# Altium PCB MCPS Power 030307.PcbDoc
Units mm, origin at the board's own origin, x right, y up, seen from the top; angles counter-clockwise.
Board outline 144.17 x 67.63 mm, 2 copper layers (Top Layer, Bottom Layer); 51 components, 22 nets, 115 pads, 4 vias.
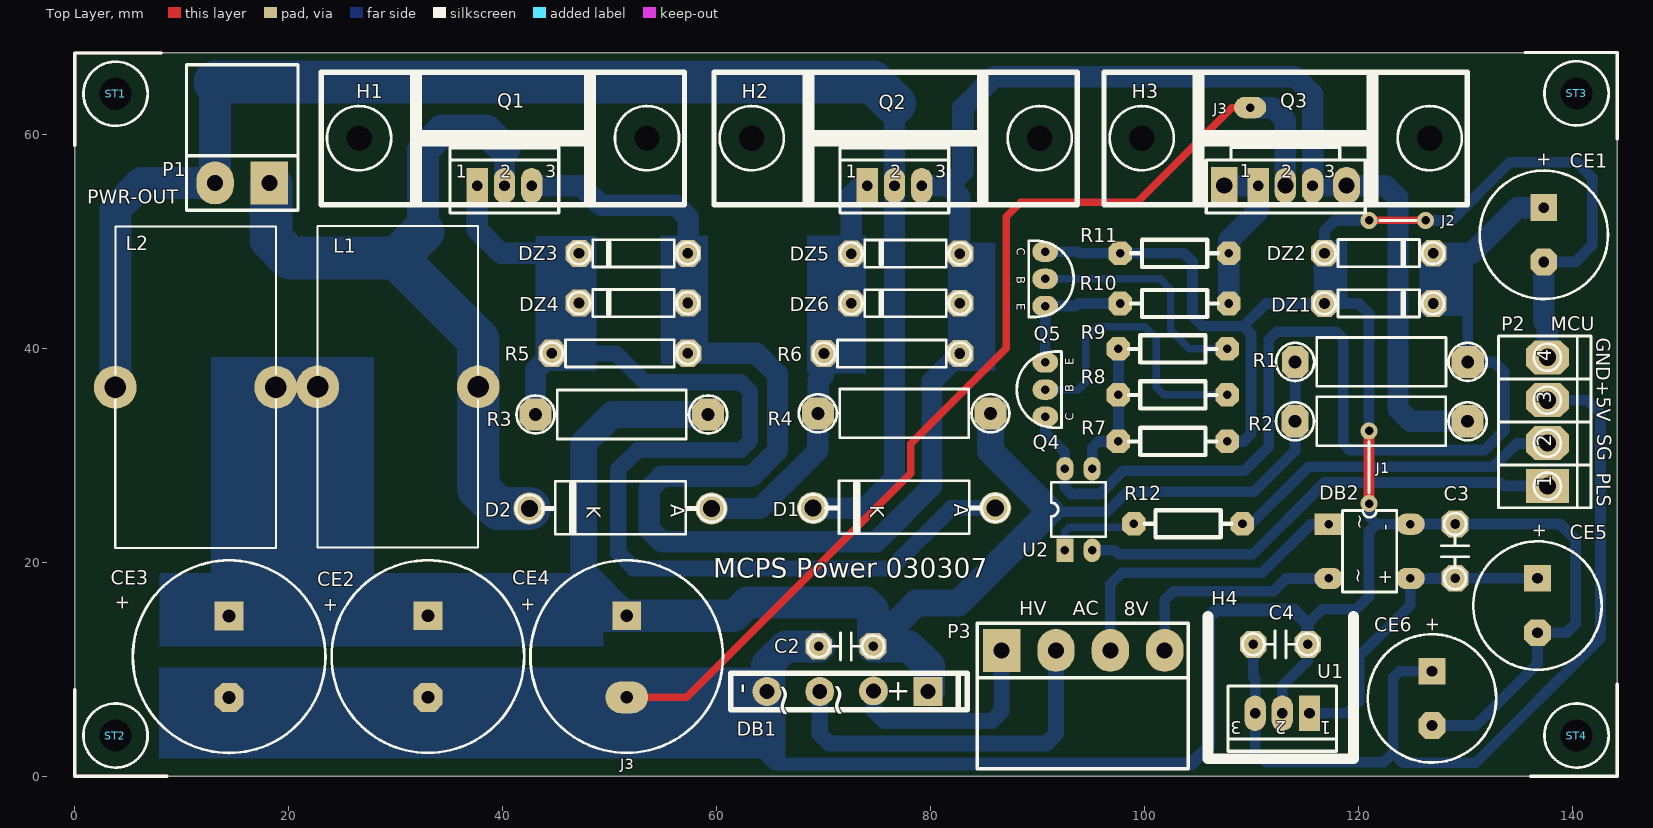
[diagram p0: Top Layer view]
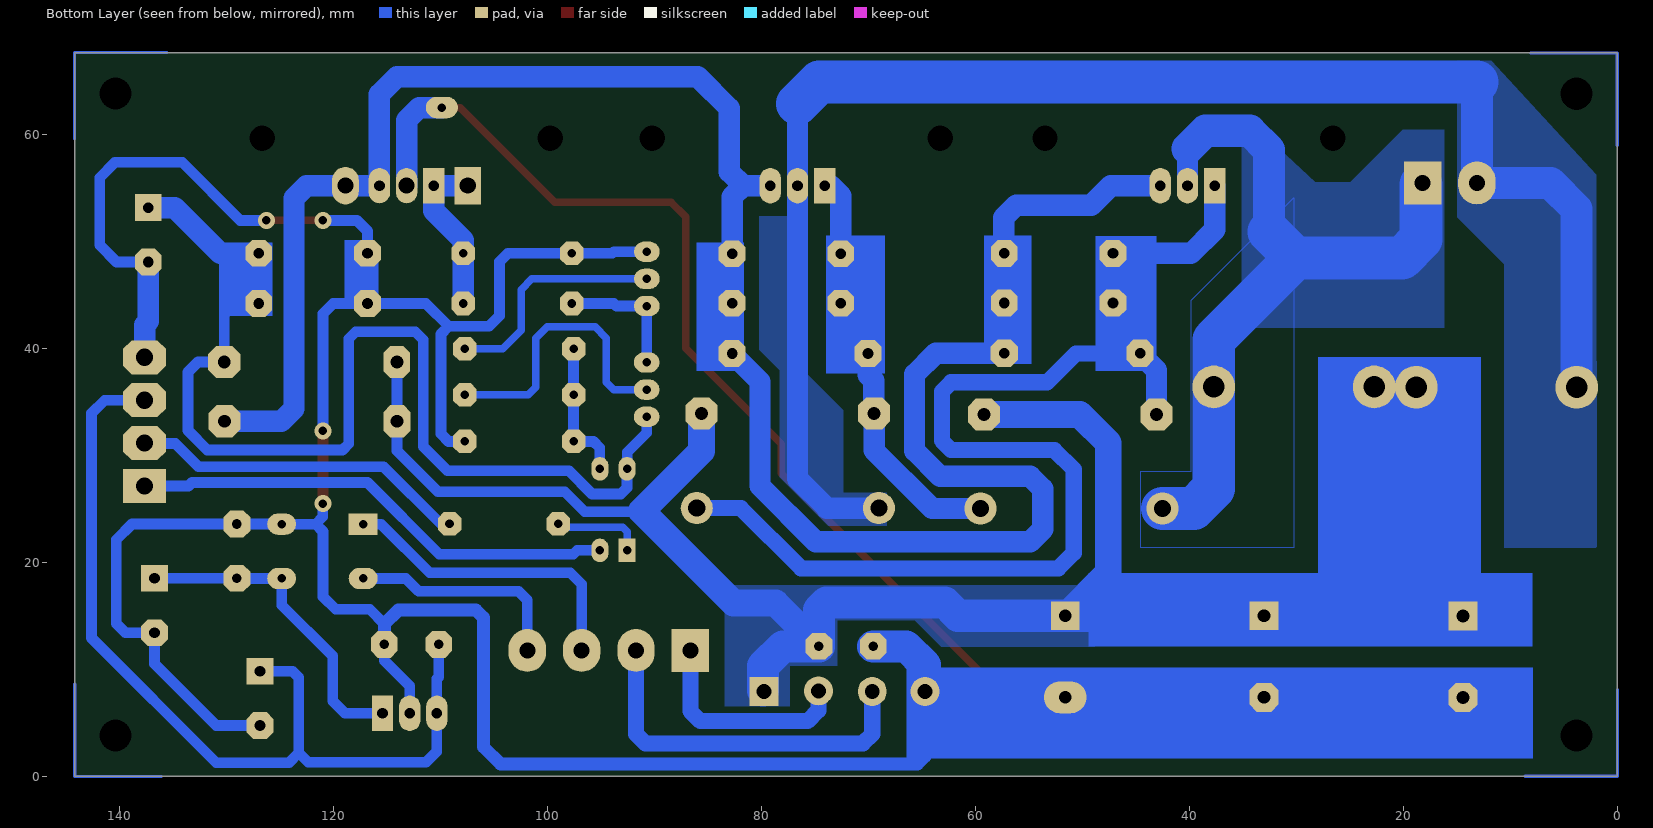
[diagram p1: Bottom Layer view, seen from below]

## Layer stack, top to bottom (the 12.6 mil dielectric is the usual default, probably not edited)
Top Solder: solder mask 0.0102, Solder Resist, Dk 3.5
Top Layer: signal copper 0.0356
Dielectric1: dielectric 0.32, FR-4, Dk 4.8
Bottom Layer: signal copper 0.0356
Bottom Solder: solder mask 0.0102, Solder Resist, Dk 3.5

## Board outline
0,-0.01 0,67.62 144.17,67.62 144.17,-0.01

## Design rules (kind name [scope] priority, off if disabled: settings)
Clearance [All] p1: gap=0.3 ignorepadtopadclearanceinfootprint=FALSE
ComponentClearance [All] p1 off: gap=0.254 collisioncheckmode=3 verticalgap=0.254 showdistances=FALSE
PolygonConnect [All] p1: connectstyle=Direct reliefconductorwidth=1 reliefentries=4 polygonreliefangle="90 Angle" airgapwidth=0.3
RoutingVias [All] p1: holewidth=0.711 width=1.27 viastyle="Through Hole" minholewidth=0.711 minwidth=1.27 maxholewidth=0.711 maxwidth=1.27
SilkToSolderMaskClearance SilkscreenOverComponentPads [IsPad] p1: minsilkscreentomaskgap=0.254 clearancetoexposedcopper=TRUE
SolderMaskExpansion [All] p1: expansion=0.102 istentingtop=FALSE
UnRoutedNet [All] p1: checkbadconnections=TRUE
Width [All] p1: maxlimit=5 minlimit=0.3 preferedwidth=0.7 minimp=50.000000 maximp=50.000000 favimp=50.000000
27 further rules are at their usual default settings.

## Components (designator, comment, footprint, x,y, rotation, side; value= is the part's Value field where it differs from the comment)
C2 "100N" c2P 74.62,12.15 r180 top locked
C3 "100N" c2P 129.01,18.5 r90 top locked
C4 "100N" c2P 110.15,12.33 r0 top locked
CE1 "470M/25" cap2p12 137.33,53.15 r0 top locked
CE2 "4700M/50" CAP3P5#1 33.01,14.85 r0 top locked
CE3 "4700M/50" CAP3P5#1 14.43,14.838 r0 top locked
CE4 "4700M/50" CAP3P5#2 51.59,14.85 r0 top locked
CE5 "1000M/25" cap2p12 136.735,18.5 r0 top locked
CE6 "220M/25" cap2p12 126.88,9.82 r0 top locked
D1 "1N5822" D54 86.03,25.07 r270 top locked
D2 "1N5822" D54 59.52,25.03 r270 top locked
DB1 "4Amp" "BRG GBU" 64.703,7.93 r270 top locked
DB2 "4Amp" "BRG F" 121.02,21.03 r90 top locked
DZ1 "18V" D4P 116.801,44.191 r180 top locked
DZ2 "18V" D4P 116.801,48.89 r180 top locked
DZ3 "18V" D4P 57.297,48.872 r0 top locked
DZ4 "18V" D4P 57.297,44.232 r0 top locked
DZ5 "18V" D4P 82.73,48.85 r0 top locked
DZ6 "18V" D4P 82.73,44.21 r0 top locked
H1 "HeatSink-Q1" heatsink2 56.957,65.782 r90 top locked
H2 "HeatSink-Q2" heatsink2 93.66,65.782 r90 top locked
H3 "HeatSink-Q3" heatsink2 130.109,65.782 r90 top locked
H4 "HeatSink-U1" heatsink5 115.282,5.977 r180 top locked
L1 "100uH/1A" Inductor-Brown 37.681,29.684 r90 top locked
L2 "100uH/1A" Inductor-Brown 3.819,43.066 r270 top locked
P1 "120Vpp/10KHz" 2EDG 19.24,75.409 r0 top locked
P2 "MCU" DSIP4 137.64,27.124 r180 top locked
P3 "40,8 Vac" 4EDG 86.63,11.76 r180 top locked
Q1 "" TO220T#1 37.626,55.198 r0 top locked
Q2 "IRFP4568" TO220T#1 74.075,55.198 r0 top locked
Q3 "IRFP4568" TO220T#2 110.61,55.2 r0 top locked
Q4 "BC337" CBE-BC546 90.71,38.68 r180 top locked
Q5 "BC327" CBE-BC546 90.7,43.95 r0 top locked
R1 "1K/1W" w1#1 122.125,38.73 r0 top locked
R2 "2K2/1W" w1#1 122.114,33.18 r0 top locked
R3 "1K/1W" w1#2 51.134,33.816 r180 top locked
R4 "1K/1W" w1#2 77.523,33.921 r180 top locked
R5 "10K" R5P 44.597,39.533 r0 top locked
R6 "4K7" R5P 82.73,39.51 r180 top locked
R7 "2K2" R4P 97.55,31.3 r90 top locked
R8 "220R" R4P 97.55,35.64 r90 top locked
R9 "220R" R4P 97.55,39.94 r90 top locked
R10 "47R" R4P 97.71,44.19 r90 top locked
R11 "10K" R4P 97.71,48.88 r90 top locked
R12 "1K" R4P 109.14,23.6 r270 top locked
ST1 "STUD" CORNER 0.01,67.6 r0 top locked
ST2 "STUD" CORNER 0,0 r90 top locked
ST3 "STUD" CORNER 144.17,67.64 r270 top locked
ST4 "STUD" CORNER 144.17,0 r180 top locked
U1 "LM7805" TO220T#1 115.4,5.89 r180 top locked
U2 "PC817" DIP4 92.55,21.12 r90 top locked

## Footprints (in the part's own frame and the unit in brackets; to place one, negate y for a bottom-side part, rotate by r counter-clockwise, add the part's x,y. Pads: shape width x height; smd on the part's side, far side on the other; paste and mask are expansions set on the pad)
2EDG [mm]
  rect 3.5x4 hole 1.5: 1(-1.045,-19.957)
  oval 3.5x4 hole 1.5: 2(-6.125,-19.957)
  silkscreen extent -8.79,-22.5 1.62,-8.91
4EDG [mm]
  rect 3.5x4 hole 1.5: 1(0,0)
  oval 3.5x4 hole 1.5: 2(-5.08,0) 3(-10.16,0) 4(-15.24,0)
  silkscreen extent -17.44,-2.54 2.29,11.05
"BRG F" [mm]
  rect 2x2.7 hole 0.8: 1(2.54,3.81)
  oval 2x2.7 hole 0.8: 2(2.54,-3.81) 3(-2.54,3.81) 4(-2.54,-3.81)
  silkscreen extent -3.81,-2.54 3.81,2.54
"BRG GBU" [mm]
  round 2.7 hole 1.4: 1(0,4.928) 2(0,0) 3(-0.051,9.957)
  rect 2.7x2.7 hole 1.4: 4(0,15.037)
  silkscreen extent -1.7,-3.41 1.7,18.69
c2P [mm]
  oct 2.5x2.5 hole 0.9: 1(0,0) 2(5.08,0)
  silkscreen extent -1.02,-1.27 6.09,1.27
cap2p12 [mm]
  rect 2.5x2.5 hole 1: 1(-0.025,0)
  oct 2.5x2.5 hole 1: 2(-0.025,-5.08)
  silkscreen extent -6.02,-8.54 5.97,3.46
CAP3P5#1 [mm]
  rect 2.7x2.7 hole 1.2: 1(0,0.152)
  oct 2.7x2.7 hole 1.2: 2(0,-7.468)
  silkscreen extent -9,-12.66 9,5.34
CAP3P5#2 [mm]
  rect 2.7x2.7 hole 1.2: 1(0,0.152)
  oval 4x3 hole 1.2: 2(0,-7.468)
  silkscreen extent -9,-12.66 9,5.34
CBE-BC546 [mm]
  oval 2.4x1.9 hole 0.8: 1(0,2.54) 2(0,0) 3(0,5.08)
  silkscreen extent -1.52,-1.02 2.67,6.1
CORNER [mm]
  round 2 hole 3: 1(3.81,-3.81)
  Multi-Layer lines w0.3: 0,-8.623 0,0.013 8.09,0.013
  silkscreen extent 0,-8.62 8.09,0.01
D4P [mm]
  oct 2.5x2.5 hole 1: 1(0,0) 2(-10.16,0)
  silkscreen extent -11.18,-1.27 1.01,1.27
D54 [mm]
  round 3 hole 1.6: 1(0,0) 2(0,-17.018)
  silkscreen extent -2.54,-18.28 2.41,1.27
DIP4 [mm]
  rect 2.2x1.6 hole 0.8: 1(0,0)
  oval 2.2x1.6 hole 0.8: 2(0,-2.54) 3(7.62,-2.54) 4(7.62,0)
  silkscreen extent 1.27,-3.81 6.35,1.27
DSIP4 [mm]
  rect 4x3.175 hole 1.6: 1(0,0)
  oct 4x3.175 hole 1.6: 2(0,-4.013) 3(0,-8.026) 4(0,-12.04)
  silkscreen extent -4.06,-14.02 4.57,2.03
heatsink2 [mm]
  round 0 hole 2.37: 5(-6.139,30.38) 5(-6.139,3.47)
  silkscreen extent -12.37,-0.04 0.03,33.91
heatsink5 [mm]
  silkscreen extent -4.23,-8.97 9.37,4.33, body extent -3.88,-8.83 9.33,3.87, height 20.32
Inductor-Brown [mm]
  round 4 hole 2: 1(6.706,14.961) 2(6.706,-0.025)
  silkscreen extent -8.3,-0.03 21.74,15
R4P [mm]
  oct 2.2x2.2 hole 0.8: 1(0,0) 2(0,-10.16)
  silkscreen extent -1.27,-9.14 1.27,-1.02
R5P [mm]
  oct 2.54x2.54 hole 1: 1(0,0) 2(12.7,0)
  silkscreen extent -1.01,-1.27 13.72,1.27
TO220T#1 [mm]
  rect 2x3.3 hole 1: 1(0,0)
  oval 2x3.3 hole 1: 2(2.54,0) 3(5.08,0)
  silkscreen extent -2.54,-2.54 7.62,3.56
TO220T#2 [mm]
  rect 2x3.3 hole 1: 1(0,0)
  oval 2x3.3 hole 1.5: 2(2.54,0)
  oval 2x3.3 hole 1: 3(5.08,0)
  silkscreen extent -4.86,-2.54 10.01,3.56
w1#1 [mm]
  oct 2.5x3 hole 1.2: 1(-8.064,0)
  oct 3x3 hole 1.2: 2(8.064,0)
  silkscreen extent -9.84,-2.29 9.84,2.29
w1#2 [mm]
  oct 3x3 hole 1.2: 1(-8.064,0) 2(8.064,0)
  silkscreen extent -9.84,-2.29 9.84,2.29

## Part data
C2 C3 C4: library part C
CE1 CE2 CE3 CE4 CE5 CE6: library part E
D1 D2: library part D
DB1 DB2: library part BRIDGE
DZ1 DZ2 DZ3 DZ4 DZ5 DZ6: library part DZ
H1 H2 H3 H4 P1: library part "Header 2", "Header, 2-Pin"
L1 L2: library part INDUCTOR
P2 P3: library part "Header 4", "Header, 4-Pin"
Q1 Q2 Q3: library part "MOSFET N"
Q4: library part BC546
Q5: library part M6, "PNP"
R1 R2 R3 R4 R5 R6 R7 R8 R9 R10 R11 R12: library part R
U1: library part Regulator, "SMD"
U2: library part OPTODIP4

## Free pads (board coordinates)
  rect 2.5x3.5 hole 1.5: 2(107.435,55.2)
  oval 2.5x3.5 hole 1.5: 3(118.865,55.2)
  oval 3x2 hole 0.8: 4(109.86,62.5)

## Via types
v1: diameter 1.6, hole 0.8, Top Layer to Bottom Layer, 4 vias

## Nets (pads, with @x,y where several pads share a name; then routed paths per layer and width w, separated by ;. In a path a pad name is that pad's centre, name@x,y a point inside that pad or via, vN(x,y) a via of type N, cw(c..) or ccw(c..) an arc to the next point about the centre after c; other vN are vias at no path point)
5V: C4.1 CE6.1 P2.3 U1.3 | length 85.7
  Bottom Layer w1: C4.1 110.15,9.29 110.32,9.12 U1.3 110.32,2.334 ; 110.32,2.3 110.32,2.334 ; CE6.1 123.816,9.82 123.23,9.234 123.23,2.2 ; P2.3 141.37,35.15 142.6,33.92 142.6,12.93 130.95,1.28 124.15,1.28 123.23,2.2 ; 110.32,2.334 111.344,1.31 122.34,1.31 123.23,2.2
16V: CE1.1 DZ1.2 DZ2.2 Q4.3 R1.2 U2.4 | length 106
  Bottom Layer w1: Q4.3 90.71,32.1 92.534,30.276 92.534,28.756 U2.4 92.55,26.976 93.136,26.39 95.82,26.39 97.98,28.55 109.32,28.55 111.6,30.83 111.6,40.79 112.35,41.54 117.917,41.54 118.56,40.897 118.56,31.086 119.146,30.5 131.77,30.5 133.58,32.31 133.58,37.79 132.64,38.73 R1.2 130.19,43.16 129.159,44.191 DZ1.2
  Bottom Layer w2: DZ1.2 DZ2.2 130.56,48.89 134.82,53.15 CE1.1
AC1: DB1.3 P3.1 | length 20.3
  Bottom Layer w1.5: DB1.3 74.66,6.168 75.678,5.15 85.69,5.15 86.63,6.09 P3.1
AC2: DB1.1 P3.2 | length 34.6
  Bottom Layer w1.5: DB1.1 69.631,3.949 70.509,3.07 90.831,3.07 91.71,3.949 P3.2
AC3: DB2.1 P3.3 | length 28.9
  Bottom Layer w1: P3.3 96.79,17.95 97.86,19.02 110.987,19.02 115.537,23.57 DB2.1
AC4: DB2.3 P3.4 | length 20.9
  Bottom Layer w1: P3.4 101.87,16.47 102.7,17.3 112.03,17.3 113.22,18.49 DB2.3
GND: C2.2 C3.2 C4.2 CE1.2 CE2.2 CE3.2 CE4.2 CE5.2 CE6.2 DB1.2 DB2.2 DZ1.1 DZ2.1 P2.4 pad.4 Q3.2 Q5.3 R7.2 R11.1 U1.2 | length 424
  Top Layer w0.7: CE4.2 57.192,7.382 78.15,28.34 78.15,31.09 87.05,39.99 87.05,52.28 88.44,53.67 99.32,53.67 108.15,62.5 pad.4 ; v1@120.97,51.95 v1(126.25,51.95)
  Top Layer w1: v1(120.97,25.49) v1(120.97,32.29)
  Bottom Layer w0.7: DB1.2@64.693,7.94 DB1.2 ; CE5.2 CE5.2@136.715,13.42
  Bottom Layer w1: Q5.3 93.77,49.03 93.92,48.88 R11.1 103.67,48.88 104.46,48.09 104.46,43.04 105.45,42.05 109.22,42.05 ; R7.2 109.227,31.3 109.94,32.013 109.94,41.33 109.22,42.05 ; U1.2 112.86,8.446 115.23,10.816 C4.2 ; 115.23,14.234 116.596,15.6 119.78,15.6 120.97,16.79 120.97,22.885 121.655,23.57 ; DZ2.1 116.801,50.961 117.79,51.95 v1@120.97,51.95 ; v1(120.97,25.49) 120.979,25.481 120.979,24.246 121.655,23.57 ; v1(120.97,32.29) 120.97,43.22 119.999,44.191 DZ1.1 111.361,44.191 109.22,42.05 ; DB2.2 121.655,23.57 ; DB2.2@124.84,23.58 C3.2 ; v1(126.25,51.95) 128.69,51.95 134.13,57.39 140.4,57.39 141.84,55.95 141.84,49.65 140.26,48.07 CE1.2 ; CE6.2 130.945,4.74 136.715,10.51 136.715,13.42 139.43,13.42 140.29,14.28 140.29,22.12 138.825,23.585 C3.2@129.015,23.585
  Bottom Layer w1.2: DB1.2@64.693,7.94 64.693,1.843 65.396,1.14 104.36,1.14 105.953,2.733 105.953,14.827 106.656,15.53 113.934,15.53 115.23,14.234 C4.2
  Bottom Layer w2: pad.4 111.978,62.5 113.15,61.328 Q3.2 ; DZ1.1 116.801,46.935 DZ2.1 ; CE1.2 137.305,42.515 137.64,42.18 P2.4
  Bottom Layer w3: CE3.2 CE2.2@32.998,7.37 ; CE2.2@33.022,7.37 CE4.2@51.578,7.37 ; CE4.2 60.532,7.382 61.09,7.94 DB1.2@64.693,7.94 ; DB1.2 64.703,10.393 66.461,12.15 C2.2
  other v1: 120.97,51.96
HV: C2.1 CE2.1 CE3.1 CE4.1 DB1.4 L1.1 L2.1 R1.1 R2.1 R3.1 R4.1 | length 197.1
  Bottom Layer w0.7: CE3.1 CE3.1@14.43,15 ; DB1.4 DB1.4@79.83,8.02
  Bottom Layer w1: 91.28,24.72 96.5,24.72 98.37,26.59 110.22,26.59 114.055,30.425 114.055,33.18 R1.1@114.055,38.73
  Bottom Layer w2.5: CE4.1 47.57,19.022 47.57,31.15 50.236,33.816 R3.1 ; C2.1 78.66,16.19 82.59,16.19 91.2,24.8 85.587,30.413 R4.1
  Bottom Layer w3: CE3.1 CE2.1@32.998,14.99 ; CE3.1@14.43,15 14.43,25.43 18.78,29.78 L2.1 18.795,36.375 22.705,36.375 L1.1 ; CE2.1@33.022,14.99 CE4.1@51.578,14.99 ; CE4.1 61.602,15.002 62.86,16.26 73.91,16.26 74.62,15.55 C2.1 77.983,12.15 79.83,10.303 DB1.4@79.83,8.02
NetC3_1: C3.1 CE5.1 DB2.4 U1.1 | length 30.4
  Bottom Layer w0.7: DB2.4 DB2.4@124.835,18.495 ; C3.1@128.525,18.495 C3.1@128.53,18.5
  Bottom Layer w1: U1.1@115.403,5.893 118.915,5.893 120.065,7.043 120.065,11.235 124.83,16 DB2.4 ; DB2.4@124.835,18.495 C3.1@128.525,18.495 ; C3.1@128.53,18.5 C3.1 CE5.1
NetD1_1: D1.1 DZ3.2 DZ4.2 Q1.1 R3.2 R5.1 | length 116.3
  Bottom Layer w0.7: DZ4.2@47.023,44.118 DZ4.2@47.042,44.137
  Bottom Layer w1.5: R5.1 50.58,39.533 53.283,36.83 62.251,36.83 63.13,35.951 63.13,31.369 62.251,30.49 52.6,30.49 50.8,28.69 50.8,20.88 52.24,19.44 76.27,19.44 81.9,25.07 D1.1
  Bottom Layer w2: Q1.1 37.626,51.094 39.848,48.872 DZ3.2 DZ4.2 ; R3.2 43.069,37.956 R5.1@44.622,39.508 ; R5.1 44.597,43.697 45.018,44.118 DZ4.2@47.023,44.118
NetD1_2: D1.2 L2.2 P1.2 Q2.2 | length 144.5
  Bottom Layer w2: D1.2 73.87,25.07 76.615,27.815 76.615,62.865
  Bottom Layer w3: L2.2 3.794,52.994 6.252,55.452 P1.2 13.115,64.89
  Bottom Layer w4: 13.115,64.89 74.59,64.89 76.615,62.865
NetD2_1: D2.1 DZ5.2 DZ6.2 Q2.1 R4.2 R6.2 | length 40
  Bottom Layer w2: D2.1 64.03,25.03 69.458,30.458 R4.2 ; R4.2@69.489,33.921 69.489,36.99 70.03,37.53 R6.2 71.51,39.51 72.57,40.57 DZ6.2 DZ5.2 72.57,54.25 73.518,55.198 Q2.1
NetD2_2: D2.2 L1.2 P1.1 Q1.2 | length 71.5
  Bottom Layer w2: Q1.2 40.166,58.654
  Bottom Layer w3: 32.55,50.9 32.55,58.53 34.35,60.33 38.49,60.33 40.166,58.654
  Bottom Layer w4: P1.1@18.35,55.297 18.35,50.187 20.107,48.43 30.08,48.43 ; 32.55,50.9 30.08,48.43 ; D2.2 39.58,25.03 37.706,26.904 37.706,40.804 30.08,48.43
NetP2_1: P2.1 U2.2 | length 45.6
  Bottom Layer w1: U2.2 97.2,21.12 97.57,20.75 110.1,20.75 116.8,27.45 133.2,27.45 133.526,27.124 P2.1
NetP2_2: P2.2 R12.1 | length 31.6
  Bottom Layer w1: R12.1 109.97,23.6 115.31,28.94 132.6,28.94 134.761,31.101 137.604,31.101 P2.2
NetQ3_1: pad.2 Q3.1 R10.2 R11.2 | length 15.3
  Bottom Layer w2: pad.2 Q3.1 110.61,52.85 107.87,50.11 R11.2 R10.2
NetQ4_1: Q4.1 R8.2 | length 27.2
  Bottom Layer w0.7: Q4.1 93.802,36.14 94.48,36.818 94.48,40.96 95.52,42 100.02,42 101.08,40.94 101.08,36.36 101.8,35.64 R8.2
NetQ4_2: Q4.2 Q5.2 R10.1 | length 12.4
  Bottom Layer w1: Q4.2@90.704,38.68 90.704,43.95 93.54,43.95 93.78,44.19 R10.1
NetQ5_1: Q5.1 R9.2 | length 22
  Bottom Layer w0.7: Q5.1 101.44,46.49 102.45,45.48 102.45,41.67 104.18,39.94 R9.2
NetR7_1: R7.1 R8.1 R9.1 U2.3 | length 13.3
  Bottom Layer w1: U2.3 95.09,30.714 95.676,31.3 R7.1 ; R7.1@97.55,31.34 R8.1 R9.1
NetR12_2: R12.2 U2.1 | length 8.5
  Bottom Layer w0.7: U2.1 92.55,22.86 92.97,23.28 98.66,23.28 R12.2
PGND: DZ3.1 DZ4.1 DZ5.1 DZ6.1 pad.3 Q1.3 Q2.3 Q3.3 R2.2 R5.2 R6.1 | length 209.4
  Bottom Layer w2: Q1.3 47.342,55.198 49.17,53.37 56.188,53.37 57.36,52.198 57.36,48.935 DZ3.1 DZ4.1 R5.2 63.707,39.533 65.68,37.56 65.68,30.443 63.267,28.03 54.874,28.03 53.702,26.858 53.702,23.082 54.874,21.91 74.9,21.91 80.12,27.13 80.12,36.9 R6.1 DZ6.1 DZ5.1 82.73,54.163 81.695,55.198 ; Q2.3 81.695,55.198 ; R2.2 124.852,33.18 123.68,34.352 123.68,54.028 122.508,55.2 Q3.3 115.69,63.75 114.05,65.39 85.95,65.39 82.98,62.42 82.98,56.483 81.695,55.198
pads on no net: H1.5 H2.5 H3.5 ST1.1 ST2.1 ST3.1 ST4.1

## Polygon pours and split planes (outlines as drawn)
HV on Bottom Layer "NONET_L-01_P-001" (solid, pour order 4): 48.82,17.859 83.435,17.859 83.435,6.56 77.35,6.56 77.35,10.33 72.92,10.33 72.92,14.59 65.68,14.59 63.18,12.09 63.15,12.12 48.82,12.12
NetD1_2 on Bottom Layer "NONET_L-01_P-001" (solid, pour order 3): 75.66,52.35 80.17,52.35 80.17,39.85 78.28,37.96 78.28,27.95 73.74,23.41 68.27,23.41 68.27,26.5 72.35,26.5 72.35,34.21 75.66,37.52
NetD2_2 on Bottom Layer "NONET_L-01_P-001" (solid, pour order 2): 30.25,54.06 30.25,21.36 44.52,21.36 44.52,28.49 39.83,28.49 39.83,42.92 39.83,44.48
NetD2_2 on Bottom Layer "NONET_L-01_P-001" (solid, pour order 1): 16.158,60.45 20.04,60.45 24.96,55.53 28.22,55.53 32.311,59.29 35.086,59.29 35.086,41.91 16.158,41.91
NetD1_2 on Bottom Layer "NONET_L-01_P-001" (solid, pour order 0): 1.927,21.38 10.58,21.38 10.58,47.84 14.98,52.24 14.98,66.87 11.794,66.87 1.961,56.201

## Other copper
Bottom Layer:
  rectangle net GND: 116.37,43.73 118.94,50.14
  rectangle net 16V: 125.691,43 130.68,49.906
  region net PGND: 86.077,49.872 81.627,49.872 81.627,37.892 86.077,37.892
  rectangle net PGND: 54.75,38.55 59.2,50.53
  rectangle net NetD2_1: 68.46,37.642 73.94,50.53
  rectangle net NetD1_1: 43.047,37.902 48.747,50.5
  rectangle net HV: 7.92,12.12 49.43,18.98
  rectangle net HV: 12.72,18.1 27.99,39.19
  rectangle net GND: 7.9,1.68 66.41,10.16

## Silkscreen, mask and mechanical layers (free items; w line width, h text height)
Top Overlay:
  circle w0.254: c126.639,59.643 r3
  circle w0.254: c99.729,59.643 r3
  circle w0.254: c90.19,59.643 r3
  circle w0.254: c63.28,59.643 r3
  circle w0.254: c53.487,59.643 r3
  circle w0.254: c26.577,59.643 r3
  lines w0.254: 121.97,51.95 123.25,51.95 125.36,51.95
  lines w0.3: 120.96,26.5 120.96,31.29
  text "J3" at 106.4,61.9 h1
  text "PWR-OUT" at 1.16,53.52 h1.3
  text "J2" at 127.71,51.47 h1
  text "MCU" at 137.93,41.66 h1.3
  text "GND" at 142.2,40.98 h1.3 r270
  text "+5V" at 142.24,36.97 h1.3 r270
  text "SG" at 142.29,31.96 h1.3 r270
  text "PLS" at 142.24,28.37 h1.3 r270
  text "J1" at 121.61,28.33 h1
  text "MCPS Power 030307" at 59.69,18.58 h1.8
  text "HV" at 88.28,15.03 h1.3
  text "AC" at 93.26,15.03 h1.3
  text "8V" at 98.06,15.01 h1.3
  text "J3" at 50.97,0.66 h1
Mechanical 1:
  the board outline again, w0.3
